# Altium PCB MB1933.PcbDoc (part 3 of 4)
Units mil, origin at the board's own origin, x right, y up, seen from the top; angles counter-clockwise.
Board outline 2755.91 x 3937.01 mil, 4 copper layers (Top Layer, GND, POWER, Bottom Layer), stack 60.63 mil thick; 228 components, 185 nets, 918 pads, 786 vias.
Unrouted connection lines stored in the file: 160.
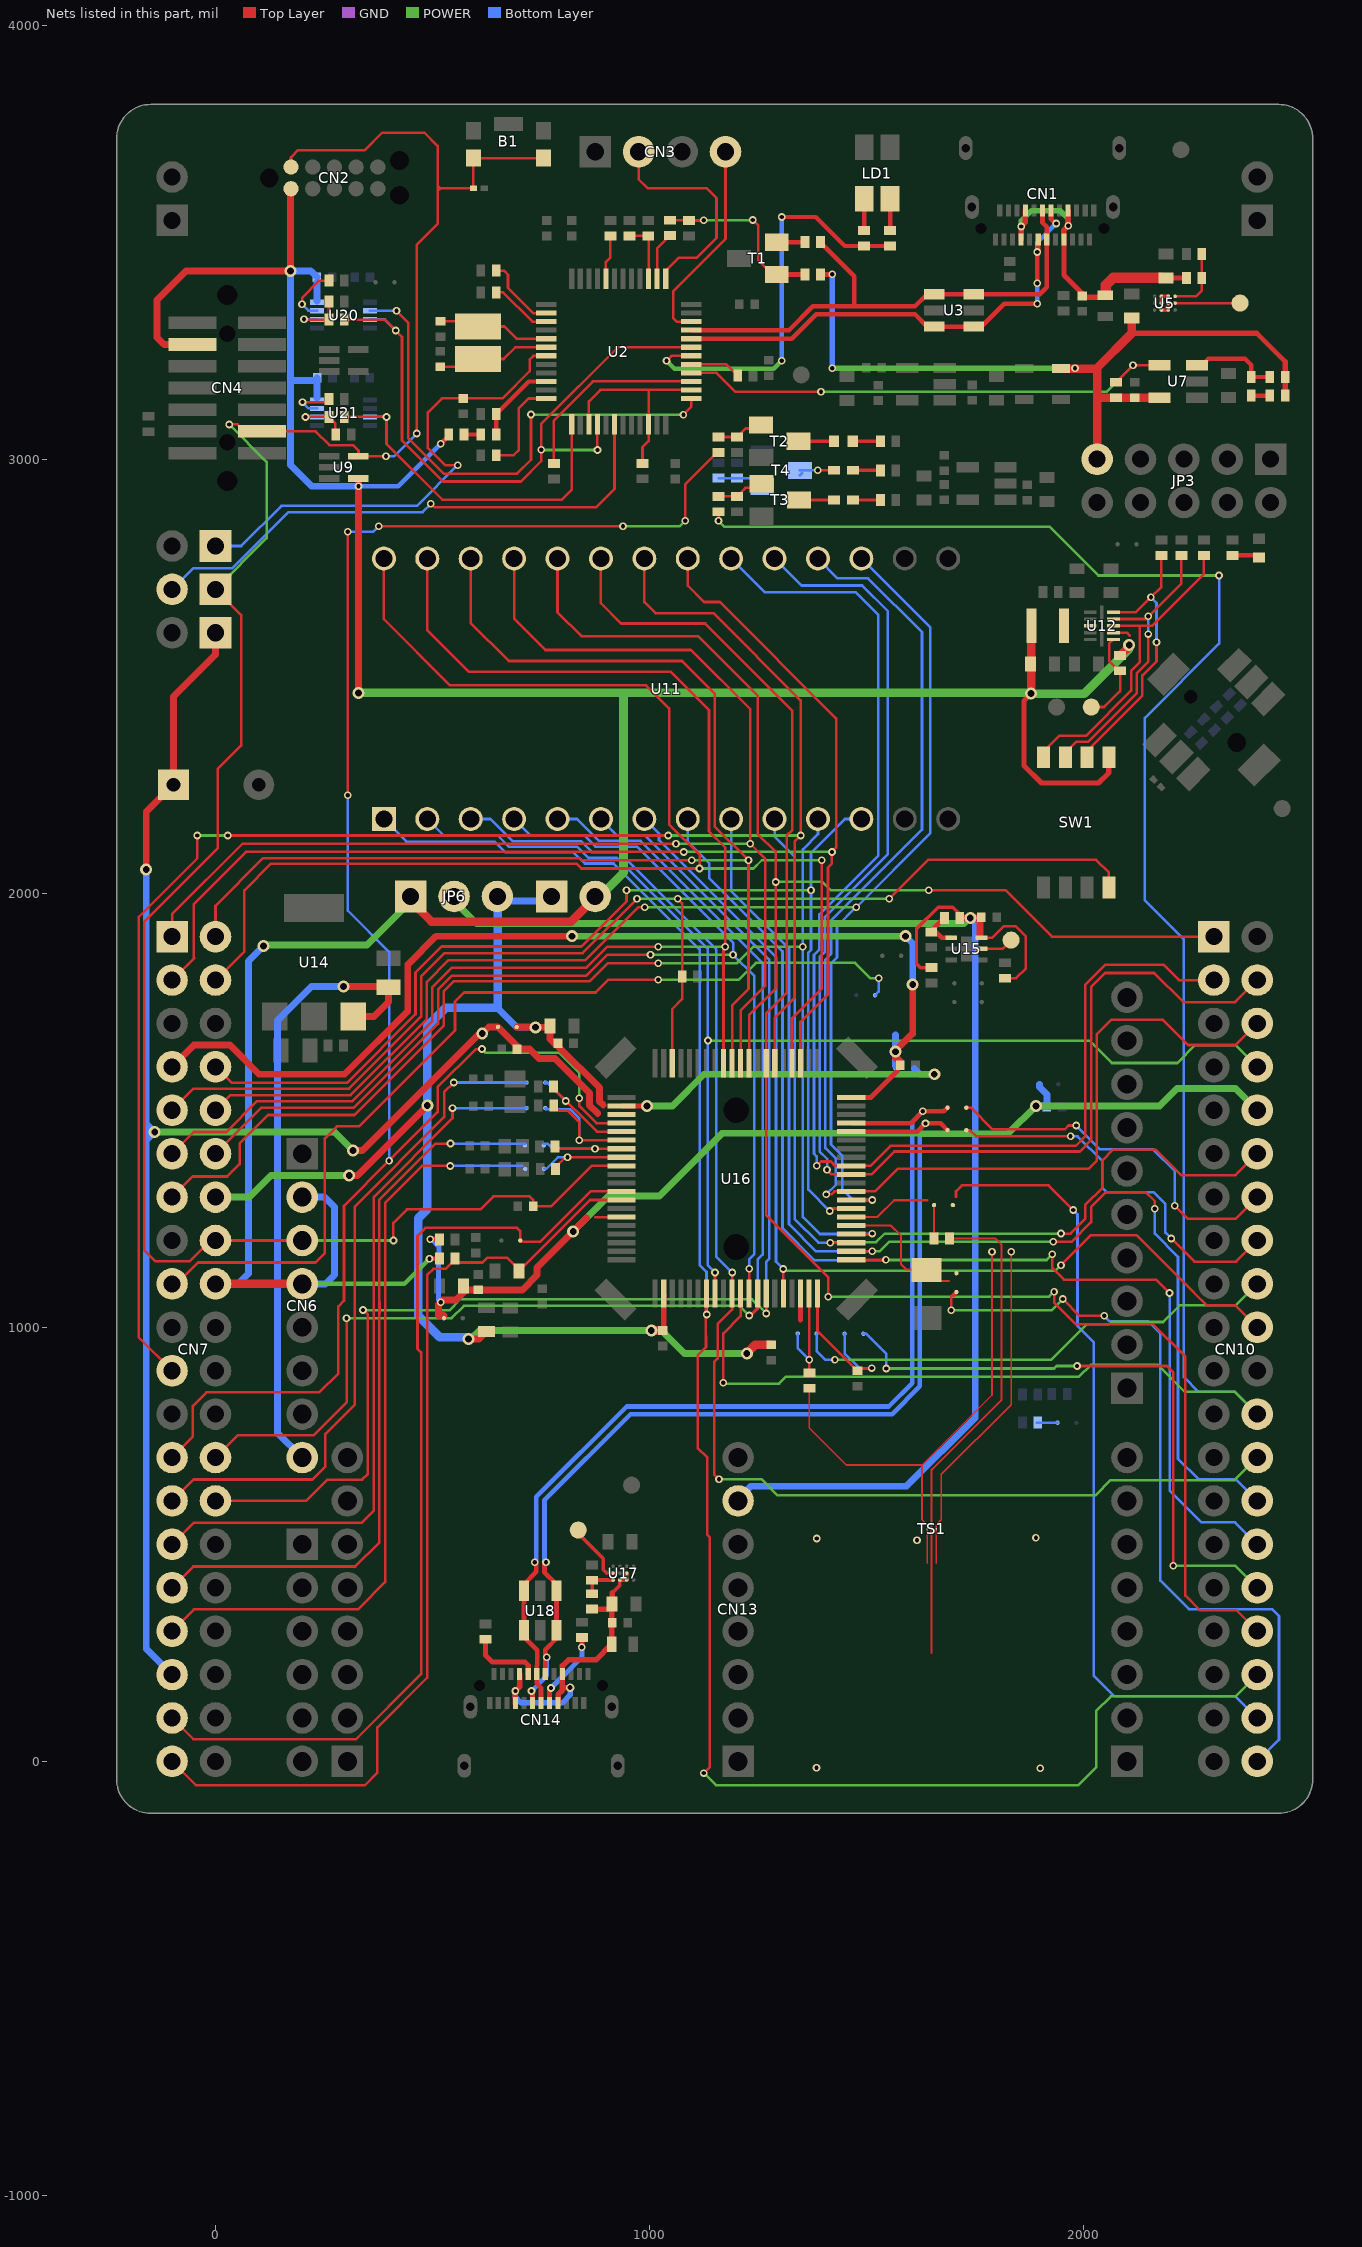
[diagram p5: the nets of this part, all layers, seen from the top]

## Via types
v1: diameter 17.72, hole 9.84, Top Layer to Bottom Layer, tented both sides, 740 vias
v2: diameter 27.56, hole 15.75, Top Layer to Bottom Layer, tented both sides, 45 vias
v3: diameter 19.68, hole 11.81, Top Layer to Bottom Layer, tented both sides, 1 vias

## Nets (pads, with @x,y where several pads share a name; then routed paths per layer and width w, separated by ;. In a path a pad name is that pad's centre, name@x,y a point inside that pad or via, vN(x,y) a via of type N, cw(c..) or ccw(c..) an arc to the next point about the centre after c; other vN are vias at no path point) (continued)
NetCN7_17: CN7.17 SB13.2 | length 2185.5
  Top Layer w5.98: CN7.17@-100,1100 -89.3,1100 -40.05,1149.25 230.25,1149.25 252.02,1171.02 252.02,1435.02 280.03,1463.03 331.03,1463.03 551.76,1683.76 551.76,1750.59 572.48,1771.32 875.78,1771.32 905.41,1800.96 v1(1020,1800.96)
  POWER w5.98: v1(1020,1800.96) 1205.96,1800.96 1244.81,1839.81 1473.28,1839.81 1509.09,1804 v1(1528,1804)
  Bottom Layer w5.98: SB13.2@1519.62,1765 1528,1773.38 v1(1528,1804)
NetCN7_27: CN7.27 SB16.2 | length 1560.7
  Top Layer w5.98: CN7.27@-100,600 -50.65,649.35 223.35,649.35 253.32,679.31 253.32,754.31 321,822 321,1278 527,1484 527,1541.7 v1(549.22,1563.92)
  Bottom Layer w5.98: v1(549.22,1563.92) SB16.2@716.54,1563.92
NetCN7_29: CN7.29 SB18.2 | length 1669.9
  Top Layer w5.98: CN7.29@-100,500 -50.36,549.64 335.96,549.64 364.69,578.37 364.69,1037.03 364.85,1037.19 364.85,1052.81 364.69,1052.97 364.69,1300.38 546,1481.69 v1(546,1505)
  Bottom Layer w5.98: v1(546,1505) 715.75,1505 716.11,1505.35 SB18.2@716.54,1504.92
NetCN7_31: CN7.31 SB19.2 | length 1699.4
  Top Layer w5.98: CN7.31@-100,400 -51,449 321.9,449 377.67,504.77 377.67,1031.65 377.83,1031.81 377.83,1058.19 377.67,1058.35 377.67,1293.99 506.95,1423.27 v1(541.64,1423.27)
  Bottom Layer w5.98: v1(541.64,1423.27) SB19.2@713.09,1423.29
NetCN7_33: CN7.33 SB20.2 | length 1762.6
  Top Layer w5.98: CN7.33@-100,300 -49.67,350.33 328.06,350.33 390.66,412.93 390.66,1026.27 390.82,1026.44 390.82,1063.56 390.66,1063.73 390.66,1286.66 475.79,1371.79 v1(541.15,1371.79)
  Bottom Layer w5.98: v1(541.15,1371.79) 706.7,1371.79
NetCN10_14: CN10.14 SB7.1 | length 851.6
  Top Layer w5.98: SB7.1@1729.77,1505.93 1740.03,1505.93 1790.03,1455.93 1956.52,1455.93 1965.59,1465 v1(1982.95,1465) ; v1(2210,1280) 2240.36,1249.64 2349.64,1249.64 CN10.14@2400,1300
  Bottom Layer w5.98: v1(1982.95,1465) 2037.95,1410 2160,1410 2210,1360 v1(2210,1280)
NetCN10_16: CN10.16 SB8.1 | length 891.2
  Top Layer w5.98: SB8.1@1729.68,1454.17 1737.56,1454.17 1752.7,1439.03 1753.67,1440 v1(1970,1440) ; v1(2201.98,1204.55) 2255.21,1151.32 2351.32,1151.32 CN10.16@2400,1200
  Bottom Layer w5.98: v1(1970,1440) 1986.18,1440 2043.12,1383.06 2043.12,1321.47 2053.24,1311.36 2160.69,1311.36 2188.39,1283.65 2188.39,1218.13 v1(2201.98,1204.55)
NetCN10_18: CN10.18 SB23.1 | length 1136.3
  POWER w5.98: v1(1427,925) 1925,925 2007.47,1007.47 2060.59,1007.47 2065.24,1012.12 2183.15,1012.12 2221.46,1050.43 2350.43,1050.43 CN10.18@2400,1100
  Bottom Layer w5.98: SB23.1@1384.78,985.47 1384.78,945.22 1405,925 v1(1427,925)
NetCN10_32: CN10.32 SB22.1 | length 1435.4
  Top Layer w5.98: v1(1985,910.96) 2191.64,910.96 2206.7,895.9 v1(2206.7,450.82)
  POWER w5.98: v1(1545,905) 1932.01,905 1937.97,910.96 v1(1985,910.96) ; v1(2206.7,450.82) 2349.18,450.82 CN10.32@2400,400
  Bottom Layer w5.98: SB22.1@1492.69,985 1499.25,985 1545,939.25 v1(1545,905)
NetCN10_38: CN10.38 SB9.1 | length 1821.3
  Top Layer w5.98: 1706,1300.47 1706,1313.18 1719.82,1327 1919.39,1327 v1(1976,1270.39)
  Bottom Layer w5.98: v1(1976,1270.39) 1986,1260.39 1986,1003 2023.24,965.76 2023.24,197.77 2071.17,149.84 2350.16,149.84 CN10.38@2400,100
NetCN10_40: CN10.40 SB11.1 | length 1808.8
  Top Layer w5.98: v1(1695,1039) 1695,1071.02 SB11.1@1705.3,1081.31 ; 1702,1072.7 1705.3,1076 ; v1(1952,1065) 1990.68,1026.32 v1(2047.45,1026.32)
  POWER w5.98: v1(1695,1039) 1926,1039 v1(1952,1065)
  Bottom Layer w5.98: v1(2047.45,1026.32) 2060.17,1013.59 2149.35,1013.59 2176.78,986.16 2176.78,416.18 2242.23,350.73 2433.87,350.73 2450.11,334.49 2450.11,50.11 CN10.40@2400,0
NetCN14_A5: CN14.A5 R64.1 | length 165.2
  Top Layer w11.81: R64.1@622,281.28 622,244.48 637.91,228.57 713.2,228.57 720.47,221.3 CN14.A5@720.47,200.98
NetCN14_B5: CN14.B5 R63.1 | length 182
  Top Layer w11.81: CN14.B5@769.68,134.06 769.68,165.68 v1(773,169) ; v1(844,263) R63.1@844,285.28
  Bottom Layer w11.81: v1(773,169) 844,240 v1(844,263)
NetJP5_2: JP5.2 U2.18 | length 1270.8
  Top Layer w5.98: v1(496,2897) 503.69,2889.31 877.31,2889.31 919.16,2931.16 U2.18@919.16,3080.68
  Bottom Layer w5.98: JP5.2@-100,2700 -51,2749 39,2749 168,2878 477,2878 v1(496,2897)
NetL1_1: L1.1 U12.3
NetLD1_1: LD1.1 R7.1 | length 73
  Top Layer w10: R7.1@1554.19,3526.64 LD1.1@1554.19,3599.61
NetLD1_2: LD1.2 R6.2 | length 73.1
  Top Layer w10: R6.2@1494.62,3527.07 LD1.2@1494.62,3600.12
NetLD2_1: LD2.1 R22.1 | length 42.9
  Top Layer w10: LD2.1@2385.8,3146.16 R22.1@2428.75,3146.16
NetLD2_2: LD2.2 R20.1 U7.3 | length 207.9
  Top Layer w10: U7.3@2261.17,3216.37 2272.39,3216.37 2287.45,3231.44 2371.7,3231.44 2385.8,3217.34 LD2.2@2385.8,3189.46 R20.1@2429.08,3189.49
NetLD3_1: LD3.1 R32.1 | length 119.2
  Top Layer w5.98: LD3.1@1476.22,3041.28 R32.1@1531.9,3041.28
  Top Layer w7.87: LD3.1@1468.34,3041.28 1476.22,3041.28 R32.1@1531.9,3041.28
NetLD3_2: LD3.2 T2.3 | length 89.5
  Top Layer w5.98: T2.3@1343.44,3033.3 T2.3@1351.32,3033.3
  Top Layer w8: T2.3@1343.44,3041.28 LD3.2@1425.04,3041.28
NetLD4_1: LD4.1 R36.1 | length 119.2
  Top Layer w5.98: LD4.1@1476.22,2974.16 R36.1@1531.9,2974.16
  Top Layer w8: LD4.1@1468.34,2974.16 R36.1@1531.9,2974.16
NetLD4_2: LD4.2 T4.3 | length 85.6
  Top Layer w5.98: v1(1387.31,2974.16) LD4.2@1425.04,2974.16
  Bottom Layer w5.98: T4.3@1346.27,2974.16 v1(1387.31,2974.16) ; T4.3@1346.69,2963.13 T4.3@1351.51,2967.95
NetLD5_1: LD5.1 R39.1 | length 63.6
  Top Layer w5.98: LD5.1@1468.34,2905.94 R39.1@1531.9,2905.94
NetLD5_2: LD5.2 T3.3 | length 80.9
  Top Layer w5.98: T3.3@1344.1,2905.94 LD5.2@1425.04,2905.94
NetLD6_1: LD6.1 R42.2 | length 56.1
  Top Layer w10: R42.2@2343,2778.29 LD6.1@2399.08,2778.29
NetR1_1: R1.1 R5.2 R12.1 T1.1 | length 411.4
  Top Layer w5.98: R1.1@1046.9,3550.57 1090.14,3550.57 R5.2@1091,3549.72 1124,3549.72 v1(1124.71,3550.43) ; v1(1237.51,3551.12) 1250.6,3538.03 1250.6,3458.01 1283.6,3425.01 T1.1@1292.98,3425.01
  Top Layer w11.81: T1.1@1292.98,3425.01 R12.1@1358.28,3425
  POWER w5.98: v1(1124.71,3550.43) 1236.82,3550.43 v1(1237.51,3551.12)
NetR2_2: R2.2 U2.44 | length 103.2
  Top Layer w5.98: U2.44@899.47,3415.32 899.47,3454.72 909.75,3465 R2.2@909.75,3514.31
NetR8_2: R8.2 T1.2 | length 65.4
  Top Layer w5.98: R8.2@1358.1,3499.81 R8.2@1358.28,3500
  Top Layer w10.63: T1.2@1292.98,3499.81 R8.2@1358.1,3499.81
NetR9_2: R9.2 R13.1 U5.C1 | length 150.8
  Top Layer w5.98: U5.C1@2210.79,3375.25 2259.11,3375.25 2272.31,3388.45 R13.1@2272.31,3417.29 R9.2@2272.31,3472.31
NetR11_1: R11.1 U2.2 | length 173.2
  Top Layer w5.98: R11.1@646.72,3434.38 664.29,3434.38 673.83,3424.84 673.83,3394.58 731.82,3336.58 U2.2@761.68,3336.58
NetR14_1: R14.1 U20.7 | length 134.1
  Top Layer w5.98: v1(199.52,3356.63) 199.52,3371.81 238.96,3411.25 R14.1@261.51,3411.25
  Bottom Layer w5.98: v1(199.52,3356.63) 214.13,3342.01 233.78,3342.01 U20.7@233.95,3341.84
NetR15_1: R15.1 U2.3 | length 142.9
  Top Layer w5.98: R15.1@646.72,3384.38 662.81,3384.38 730.29,3316.9 U2.3@761.68,3316.9
NetR17_1: R17.1 R18.2 U20.6 | length 129.8
  Top Layer w5.98: v1(204.01,3322.16) 204.01,3322.01 204.69,3321.34 R18.2@261.51,3321.34 R17.1@261.51,3363.25
  Bottom Layer w5.98: v1(204.01,3322.16) U20.6@233.95,3322.16
NetR19_1: R19.1 U2.29 | length 117.3
  Top Layer w5.98: U2.29@1096.32,3218.47 1176.96,3218.47 R19.1@1202.89,3192.55
NetR23_1: R23.1 U21.7 | length 103.6
  Top Layer w5.98: v1(200.4,3131.44) 254.62,3131.44 R23.1@261.51,3138.32
  Bottom Layer w5.98: v1(200.4,3131.44) 214.7,3117.14 233.95,3117.14 U21.7@233.95,3116.98
NetR25_2: R25.2 R27.1 U21.6 | length 128.6
  Top Layer w5.98: v1(207.29,3097.28) 261.22,3097.28 R25.2@261.51,3097.58 275.9,3083.18 275.9,3057.22 R27.1@277.17,3057.22
  Bottom Layer w5.98: v1(207.29,3097.28) U21.6@233.95,3097.29
NetR30_2: R30.2 R31.2 T2.1 | length 105.6
  Top Layer w5.98: R30.2@1159.36,3051.02 R31.2@1201.29,3051.02 1220.97,3070.71 T2.1@1256.83,3070.71
NetR37_2: R37.2 R38.2 T3.1 | length 106.3
  Top Layer w5.98: R37.2@1159.35,2914.11 R38.2@1201.28,2914.11 1220.97,2933.8 T3.1@1257.52,2933.8
NetR40_2: R40.2 SW1.7 U12.10 | length 675.2
  Top Layer w5.98: SW1.7@1958,2313 1958,2324 1982.95,2348.95 2010.3,2348.95 2108.16,2446.81 2108.45,2446.81 2122.52,2460.88 2122.52,2506.88 2149,2533.36 v1(2149,2597) ; U12.10@2068.58,2631.75 2142.87,2631.75 v1(2149.12,2638) 2225,2713.88 R40.2@2225,2778.29
  Bottom Layer w5.98: v1(2149,2597) 2149,2637.88 v1(2149.12,2638)
NetR41_2: R41.2 SW1.8 U12.9 | length 731.9
  Top Layer w5.98: SW1.8@1908,2313 1908,2327 1943.51,2362.51 2005.49,2362.51 2109.53,2466.55 2109.53,2512.53 2129.63,2532.63 2129.63,2616 ; U12.9@2068.58,2616 2129.63,2616 ; R41.2@2277,2778.29 2277,2735.43 2157.57,2616 2129.63,2616
NetR43_2: R43.2 SW1.6 U12.11 | length 651.8
  Top Layer w5.98: SW1.6@2008,2313 2008,2328 2135.5,2455.5 2135.5,2501.5 2168,2534 v1(2168,2578) ; U12.11@2068.58,2647.5 2120.5,2647.5 v1(2155,2682) 2179,2706 R43.2@2179,2778.28 ; R43.2@2173,2778.29 R43.2@2176,2775.28
  Bottom Layer w5.98: v1(2155,2682) 2168,2669 v1(2168,2578)
NetR45_2: R45.2 TP4.1 U12.7 | length 216.1
  Top Layer w5.98: TP4.1@2017.6,2429 2047.08,2429 2084,2465.92 R45.2@2084,2512.28 2081.48,2512.28 2058.96,2534.81 2058.96,2574.89 U12.7@2068.58,2584.51
NetR46_1: R46.1 R47.2 U15.4 | length 90.3
  Top Layer w10.63: R47.2@1649,1913.72 1677.6,1942.31 R46.1@1682.28,1942.31 ; R47.2@1656.72,1913.72 1673.15,1897.28 U15.4@1695.04,1897.28
NetR61_2: R61.2 R62.1 U17.C1 | length 79.2
  Top Layer w8.46: R62.1@867.78,386.43 R61.2@867.78,417 868.78,418 U17.C1@916.02,418
NetR65_2: R65.2 R66.2 T4.1 | length 108.5
  Bottom Layer w5.98: R66.2@1159.35,2956.44 1231.3,2956.44 1250.99,2936.76 T4.1@1259.65,2936.76
NetR73_1: R73.1 SB24.2 | length 47.7
  Bottom Layer w5.98: R73.1@1892.32,780.3 SB24.2@1939.98,780.3
NetTP1_1: TP1.1 U5.B1 | length 149.6
  Top Layer w5.98: U5.B1@2210.79,3359.51 TP1.1@2360.4,3359.51
NetTP5_1: TP5.1 U15.2 | length 76.3
  Top Layer w5.98: U15.2@1765.12,1871.69 1812.69,1871.69 TP5.1@1833,1892
NetTP6_1: TP6.1 U17.B1 | length 141.1
  Top Layer w8.46: TP6.1@835.7,532.9 835.7,524.83 893.39,467.14 893.39,441.61 901.25,433.75 U17.B1@916.02,433.75
NRST: B1.2 B1.4 C40.2 CN2.10 CN4.12 CN6.3 CN7.16 JP5.1 U1.1 U9.5 U16.9 | length 5249.7
  Top Layer w5.98: JP5.1@0,2700 59,2641 59,2340.42 5,2286.42 5,2103.46 -163.77,1934.68 -163.77,1177.5 -138.86,1152.58 -58.96,1152.58 -11.55,1200 CN7.16@0,1200 CN6.3@200,1200 ; v1(32,3080) 51,3080 67,3064 CN4.12@107,3064 230.93,3064 262.48,3032.44 316.8,3032.44 329.42,3019.82 U9.5@329.42,3006.84 372.63,3006.84 372.78,3007 v1(393,3007) ; CN2.10@174,3673 174,3695.5 190.5,3712 344,3712 384,3752 482,3752 512,3722 512,3630 ; v1(410,1200) 410,1240.6 441.28,1271.89 610.15,1271.89 640.16,1301.91 723.38,1301.91 732,1293.29 C40.2@732,1279.07 773.67,1279.07 866.64,1372.04 U16.9@935.23,1372.04 ; v1(464,3059) 464,3494 512,3542 512,3617.52 ; U1.1@592.43,3623.76 518.24,3623.76 ; U1.1@594.7,3623.76 594.29,3624.16 B1.4@594.29,3693.5 B1.2@755.71,3693.5 ; 512,3617.52 512,3630 ; 512,3617.52 518.24,3623.76 ; 512,3630 518.24,3623.76
  POWER w5.98: JP5.1@0,2700 118,2818 118,2994 v1(32,3080) ; CN6.3@200,1200 200.26,1199.74 201.24,1200.73 202.03,1199.94 202.09,1200 v1(410,1200)
  Bottom Layer w5.98: v1(393,3007) 412,3007 v1(464,3059)
PA11: CN14.A7 CN14.B7 SB8.2 U16.56 U18.3 U18.4 | length 2367.8
  Top Layer w10.63: v1(728,162) 730.31,159.69 CN14.B7@730.31,134.06 ; CN14.A7@759.84,200.98 759.84,220.08 759.69,220.23 759.69,257.28 785.58,283.17 U18.3@785.58,302 U18.4@785.58,392.55 785.58,408 757.87,435.71 757.87,455.46 v1(761.41,459) ; U16.56@1464.76,1450.78 1616.63,1450.78 v1(1635.6,1469.76) 1670.79,1469.76 SB8.2@1686.38,1454.17
  Bottom Layer w10.63: v1(728,162) 763,197 v1(763,240) ; v1(761.41,459) 757.87,462.54 757.87,601.7 956.17,800 1558.7,800 1622.68,863.98 1622.68,1456.84 v1(1635.6,1469.76)
PA12: CN14.A6 CN14.B6 SB7.2 U16.57 U18.1 U18.6 | length 2354.2
  Top Layer w10.63: v1(735.82,459) 739.37,455.46 739.37,436.59 710.78,408 U18.6@710.78,392.55 U18.1@710.78,302 716.05,296.73 716.05,281.28 741.18,256.15 741.18,221.11 740.16,220.08 CN14.A6@740.16,200.98 740.16,179.79 750,169.94 CN14.B6@750,134.06 ; U16.57@1464.76,1470.47 1602.52,1470.47 v1(1629.6,1497.55) 1678.08,1497.55 SB7.2@1686.46,1505.93
  Bottom Layer w10.63: v1(735.82,459) 739.37,462.54 739.37,609.37 947.63,817.63 1551.4,817.63 1605.06,871.29 1605.06,1473 v1(1629.6,1497.55)
PB1: CN10.26 U11.3 U16.30 | length 3238.8
  Top Layer w5.98: v1(1160,650) 1149,661 1149,920.02 1157.02,928.03 1157.02,1007.38 1190.15,1040.52 U16.30@1190.15,1077.76 v1@1190.15,1125.89
  POWER w5.98: v1(1160,650) 1258,650 1295.02,612.98 2026.98,612.98 2062,648 2348,648 CN10.26@2400,700
  Bottom Layer w5.98: U11.3@588,2171 633.47,2171 684.51,2119.97 841.71,2119.97 867.18,2094.5 929.99,2094.5 1153.45,1871.03 1153.45,1163.03 v1(1190.37,1126.11)
PB2: CN10.24 R37.1 U16.31 | length 4912.2
  Top Layer w5.98: v1(1159.06,2857.81) 1159.35,2858.11 R37.1@1159.35,2878.68 ; v1(1170,872) 1170,985.91 1209.84,1025.75 U16.31@1209.84,1077.76
  POWER w5.98: v1(1159.06,2857.81) 1172.88,2844 1922,2844 2034,2732 v1(2312,2732) ; v1@1170,874.98 v1@1170,874.5 ; CN10.24@2400,800 2348.49,851.51 2232.98,851.51 2170.9,913.59 2016.49,913.59 1989.05,886.15 1314.17,886.15 1298.17,870.15 1171.85,870.15 v1(1170,872) ; v1(1170,872) 1167.5,872 v1@1170,874.5 ; v1(1170,872) v1@1170,874.5
  Bottom Layer w5.98: v1(2312,2732) 2312,2575 2141.06,2404.06 2141.06,1983.58 2230.72,1893.92 2230.72,885.57 2264.77,851.51 2348.49,851.51 CN10.24@2400,800
PB11: CN10.20 U11.7 U16.36 | length 2444.2
  Top Layer w5.98: U16.36@1308.26,1077.76 v1(1308.27,1134.29) ; v1(1948,1143) 2017.12,1212.12 2122.27,1212.12 2253.59,1080.8 2283.94,1050.43 2349.57,1050.43 CN10.20@2400,1000
  POWER w5.98: v1(1308.27,1134.29) 1312.07,1130.5 1935.5,1130.5 v1(1948,1143) v1@1951.34,1143
  Bottom Layer w5.98: U11.7@988,2171 1021.74,2137.26 1021.74,2122.5 1291.35,1852.89 1291.35,1151.22 v1(1308.27,1134.29)
PB12: R60.1 SB23.2 U16.39 | length 254.5
  Top Layer w5.98: U16.39@1367.32,1077.76 1368,1077.08 v1(1368,925) R60.1@1368,895
  Bottom Layer w5.98: SB23.2@1341.48,985.47 1341.48,951.53 v1(1368,925)
PB13: C50.1 SB22.2 U16.40 | length 373.5
  Top Layer w5.98: U16.40@1387,1077.76 1387,991.74 C50.1@1479,899.74 1485.26,906 v1(1512,906)
  Bottom Layer w5.98: SB22.2@1449.38,985 1449.38,939.86 1483.24,906 v1(1512,906)
PB14: CN10.30 U11.8 U16.41 | length 2804.3
  Top Layer w5.98: U16.41@1464.76,1155.51 v1(1544.5,1155.51) ; v1(1928,1168.38) 1928,1136.34 1954.34,1110 2167,1110 v1(2198,1079)
  POWER w5.98: v1(1544.5,1155.51) 1544.85,1155.15 1914.77,1155.15 v1(1928,1168.38)
  Bottom Layer w5.98: U11.8@1088,2171 1088,2119 1138,2069 1138,2034.43 1306.34,1866.09 1306.34,1228.66 1380.5,1154.5 v1@1544.5,1154.5 ; v1(2198,1079) 2198,624.58 2271.86,550.73 2349.27,550.73 CN10.30@2400,500
PB15: CN10.28 U11.9 U16.42 | length 2829.1
  Top Layer w5.98: U16.42@1464.76,1175.19 v1(1513.11,1175.18) ; v1(1930,1197) 1972,1197 2017.15,1242.15 2017.15,1276.67 2051.84,1311.36 2143.05,1311.36 2164,1290.41 v1(2164,1273)
  POWER w5.98: v1(1513.11,1175.18) 1530.07,1175.18 1551.89,1197 v1(1930,1197)
  Bottom Layer w5.98: U11.9@1188,2171 1188,2005.65 1321.17,1872.48 1321.17,1237.83 1383.97,1175.03 1512.96,1175.03 v1(1513.11,1175.18) ; v1(2164,1273) 2164,1215.87 2217.43,1162.44 2217.43,697.11 2264.3,650.23 2349.77,650.23 CN10.28@2400,600
PC2: CN7.37 SB10.2 U16.12 | length 2222.6
  Top Layer w5.98: CN7.37@-100,100 -51,51 324,51 474.02,201.02 474.02,941.98 465.49,950.51 465.49,1210.49 483.94,1228.94 694.93,1228.94 701.98,1221.89 SB10.2@701.98,1200.04 701.98,1197.08 748.18,1197.08 864.08,1312.99 U16.12@935.23,1312.99
PC3: C43.2 CN7.39 R58.2 U16.13 | length 2257.9
  Top Layer w5.98: CN7.39@-100,0 -45,-55 344,-55 373,-26 373,78 487.65,192.65 487.65,1120.26 502.22,1134.83 530.33,1134.83 551.58,1156.08 R58.2@551.58,1158.6 560.83,1149.35 615.16,1149.35 625.79,1159.98 672.45,1159.98 699.32,1133.11 C43.2@699.32,1129.96 699.42,1129.96 862.76,1293.3 U16.13@935.23,1293.3 U16.13@934.33,1294.21
PC4: CN10.36 U11.1 U16.27 | length 4298.9
  Top Layer w5.98: v1(1125,-27) 1139,-13 1139,515.98 1132.98,522 1132.98,699.89 1111,721.87 1111,935.14 1130.08,954.21 1130.08,979.68 1129.44,980.32 1129.44,1076.09 U16.27@1131.1,1077.76
  POWER w5.98: v1(1125,-27) 1152.81,-54.81 1987.83,-54.81 2029,-13.64 2029,116 2062.84,149.84 2349.84,149.84 CN10.36@2400,200
  Bottom Layer w5.98: U11.1@388,2171 440,2119 643.07,2119 668.07,2094 825.27,2094 850.74,2068.53 917.47,2068.53 1115.61,1870.39 1115.61,1143.2 1131.15,1127.66 1131.15,1030.02 v1(1131.8,1029.37)
PC5: CN10.8 U11.2 U16.28 | length 2896
  Top Layer w5.98: U16.28@1150.78,1077.76 1150.78,1125.89 v1(1151,1126.11)
  POWER w5.98: v1(1134.46,1660.57) 2013.29,1660.57 2065.05,1608.81 2215.92,1608.81 2257.11,1650 2350,1650 CN10.8@2400,1600
  Bottom Layer w5.98: U11.2@488,2171 526.56,2132.44 650.83,2132.44 676.29,2106.98 833.49,2106.98 858.96,2081.51 924.49,2081.51 1134.46,1871.54 v1(1134.46,1660.57) 1134.46,1142.71 1151,1126.17 v1(1151,1126.11)
PC6: CN10.6 U11.18 U16.49 | length 3091.9
  Top Layer w5.98: v1(1406.78,1306.22) 1419.22,1306.22 1425.99,1312.99 U16.49@1464.76,1312.99 1519.66,1312.99 1571.68,1365 2011.66,1365 2030.13,1383.47 2030.13,1674.75 2064.18,1708.8 2182.19,1708.8 2240.56,1650.43 2350.43,1650.43 CN10.6@2400,1700
  Bottom Layer w5.98: U11.18@1388,2771 1433.37,2725.63 1503.55,2725.63 1627.66,2601.51 1627.66,2146.66 1417.92,1936.92 1417.92,1860.18 1404.94,1847.19 1404.94,1413.14 1429,1389.08 1429,1328.44 v1(1406.78,1306.22)
PC8: CN10.4 U11.19 U16.51 | length 3113.3
  Top Layer w5.98: v1(1409,1363) 1419.64,1352.36 U16.51@1464.76,1352.36 1511.36,1352.36 1564,1405 1991.18,1405 2017.15,1430.97 2017.15,1784.1 2049.24,1816.18 2162.4,1816.18 2229.63,1748.95 2348.95,1748.95 CN10.4@2400,1800
  Bottom Layer w5.98: U11.19@1288,2771 1350.1,2708.9 1489.67,2708.9 1548.92,2649.64 1548.92,2090.56 1404,1945.64 1404,1864.62 1391.95,1852.57 1391.95,1405.38 1409,1388.33 v1(1409,1363)
PC9: CN10.3 U11.20 U16.52 | length 3060.4
  Top Layer w5.98: v1(1385,1372) 1395,1382 1417.64,1382 1427.6,1372.04 U16.52@1464.76,1372.04 1509.03,1372.04 1554.97,1417.98 1981.89,1417.98 2004.16,1440.26 2004.16,1789.47 2049.96,1835.27 2184.36,1835.27 2219.63,1800 CN10.3@2300,1800
  Bottom Layer w5.98: U11.20@1188,2771 1265.66,2693.34 1475.2,2693.34 1527.07,2641.47 1527.07,2087.07 1391,1951 1391,1869.98 1378.97,1857.95 1378.97,1400 1385,1393.97 v1(1385,1372)
PC10: CN7.3 U11.21 U16.63 | length 3077.5
  Top Layer w5.98: CN7.3@-100,1800 -50,1850 ; -48.68,1851.32 -50,1850 ; v1@1079,2095.15 70.15,2095.15 -50,1975 -50,1850 ; U11.21@1088,2771 1088,2708.47 1125.47,2671 1162,2671 1430,2403 1430,2105 v1(1420.15,2095.15) 1420.15,2068.15 1411,2059 1411,1767 1347.63,1703.63 U16.63@1347.63,1608.26
  POWER w5.98: v1(1079,2095) 1079.15,2095.15 v1(1420.15,2095.15)
PC11: CN7.4 U11.28 U16.64 | length 3380
  Top Layer w5.98: CN7.4@0,1800 1.11,1800 66.67,1865.56 66.67,2006.67 128.08,2068.08 831.99,2068.08 843.07,2057 v1(1115,2057) 1115.85,2057.85 1115.85,2087.94 1045.09,2158.7 1045.09,2425.91 992,2479 540.2,2479 388,2631.2 U11.28@388,2771 ; U16.64@1327.95,1608.26 1327.95,1711.95 1397,1781 v1(1397,2076)
  POWER w5.98: v1(1115,2057) 1239.49,2057 1258.49,2076 v1(1397,2076)
PC13: CN7.25 R30.1 U16.4 | length 4301.4
  Top Layer w5.98: CN7.25@-100,700 -52,748 -52,819 -21,850 239,850 283,894 283,1048.48 296,1061.48 296,1280 v1(400,1384) 512,1496 512,1553.35 599.63,1640.98 v1(614,1640.98) ; v1(305,2226) 305.11,2226.11 v1@305.11,2833 ; v1(376.19,2845.31) v1(938.79,2845.31) ; v1(838.1,1527.99) 838.1,1509.69 877.33,1470.47 U16.4@935.23,1470.47 ; v1(1082,2858.11) 1082,2941.87 1155.72,3015.59 R30.1@1159.36,3015.59
  POWER w5.98: v1(614,1640.98) 622.17,1632.82 791.24,1632.82 838.1,1585.96 v1(838.1,1527.99) ; v1(938.79,2845.31) 1069.2,2845.31 v1(1082,2858.11)
  Bottom Layer w5.98: v1(305,2226) 305,1959.64 400,1864.64 v1(400,1384) ; v1(305,2833) 363.88,2833 v1(376.19,2845.31)
PC14: R52.2 SB16.1 U16.5 | length 277.5
  Top Layer w5.98: R52.2@782.59,1549.26 780.17,1549.26 878.61,1450.82 886.72,1450.82 ; 878.55,1450.78 U16.5@935.23,1450.78
  Bottom Layer w5.98: SB16.1@759.85,1562.05 766.17,1562.05 ; SB16.1@759.85,1563.92 764.3,1563.92 766.17,1562.05 ; v1(806.96,1521.25) 766.17,1562.05
PC15: R53.2 SB18.1 U16.6 | length 345.5
  Top Layer w5.98: R53.2@779.19,1510.83 790.82,1499.2 810.96,1499.2 838.1,1472.07 v1(838.1,1431.14) ; v1@843.61,1431.1 U16.6@935.23,1431.1
  Bottom Layer w5.98: SB18.1@759.85,1504.92 762.36,1502.4 816.71,1502.4 838.1,1481.02 v1(838.1,1431.14)
PD0: CN7.21 U11.22 U16.66 | length 4125.6
  Top Layer w5.98: CN7.21@-100,900 -176.76,976.76 -176.76,1945.42 -42,2080.18 v1(-42,2133) ; v1(28,2133) v1(1043,2133) ; U11.22@988,2771 988,2670.8 1013.59,2645.21 1146.79,2645.21 1348.05,2443.95 v1(1348.05,2133) 1334.15,2119.1 1334.15,1869.19 1334.6,1868.74 1334.6,1759.6 1288.58,1713.58 U16.66@1288.58,1608.26
  POWER w5.98: v1(-42,2133) v1(28,2133) ; v1(1043,2133) v1(1348.05,2133)
PD1: CN10.34 U11.23 U16.67 | length 3734.5
  Top Layer w5.98: U11.23@888,2771 888,2668.05 934.75,2621.3 1127.96,2621.3 1329.14,2420.12 1329.14,2146 1316,2132.86 1316,1770.66 1268.89,1723.55 U16.67@1268.89,1608.26 1268.89,1258.11 1411.42,1115.58 v1(1411.42,1070.61) ; v1(1932,1082) 1932,1057.57 1982.74,1006.83 2160.17,1006.83 2234.46,932.54 2234.46,381.63 2267.92,348.17 2351.83,348.17 CN10.34@2400,300
  POWER w5.98: v1(1411.42,1070.61) 1920.61,1070.61 v1(1932,1082)
PD3: CN10.1 U11.24 U16.69 | length 2615.7
  Top Layer w5.98: U11.24@788,2771 788,2647.08 842.72,2592.36 1111.89,2592.36 1249.22,2455.03 1249.22,2136.65 1291,2094.87 v1(1291,2026) 1291,1781.09 1229.52,1719.61 U16.69@1229.52,1608.26 ; v1(1643,2007) 1819.81,2007 1926.81,1900 CN10.1@2300,1900
  POWER w5.98: v1(1291,2026) 1398.23,2026 1417.55,2006.67 1417.88,2007 v1(1643,2007)
PD4: CN7.1 U11.25 U16.70 | length 3073.6
  Top Layer w5.98: CN7.1@-100,1900 -100,1952 62,2114 v1(1061,2114) ; U11.25@688,2771 688,2632.52 760.05,2560.47 1095.53,2560.47 1232,2424 v1(1232,2114) 1266.64,2079.36 1266.64,1786.95 1209.84,1730.15 U16.70@1209.84,1608.26
  POWER w5.98: v1(1061,2114) v1(1232,2114)
PD5: CN7.2 U11.26 U16.71 | length 3024.2
  Top Layer w5.98: CN7.2@0,1900 0,1971.09 109.97,2081.06 837.37,2081.06 842.43,2076 v1(1097,2076) ; U11.26@588,2771 588,2622.87 675.87,2535 1075,2535 1149.98,2460.02 1149.98,2154 1227.96,2076.02 1227.96,1779.37 1190.15,1741.56 U16.71@1190.15,1608.26
  POWER w5.98: v1(1097,2076) v1(1228.16,2076)
PD6: CN7.11 U11.27 U16.72 | length 3238
  Top Layer w5.98: CN7.11@-100,1400 -50.06,1449.94 25.03,1449.94 96.09,1521 315.55,1521 499.82,1705.27 499.82,1783.84 543.97,1828 853.74,1828 902.74,1877 v1(1020,1877) ; U11.27@488,2771 488,2605.55 583.55,2510 1049,2510 1137,2422 1137,2142.52 1174.41,2105.11 v1(1174.41,1877) ; U16.72@1170.47,1608.26 1170.47,1868.47 v1@1176.7,1874.7
  POWER w5.98: v1(1020,1877) v1(1174.41,1877)
PD8: CN10.12 U11.10 U16.43 | length 2257.5
  Top Layer w5.98: v1(1416.41,1194.89) U16.43@1464.76,1194.88 ; v1@1948,1215.87 1969.87,1215.87 2004.16,1250.16 2004.16,1282.52 2043.12,1321.47 2043.12,1384.78 2067.72,1409.39 2165.66,1409.39 2224.61,1350.43 2350.43,1350.43 CN10.12@2400,1400
  POWER w5.98: v1(1416.41,1194.89) 1417.55,1196.03 1522.03,1196.03 1541.87,1215.87 1938.3,1215.87
  Bottom Layer w5.98: U11.10@1288,2171 1288,2131 1334.15,2084.85 1334.15,1249.7 1388.96,1194.89 v1(1416.41,1194.89)
  other v1: 1948,1216
PD9: CN7.13 U11.11 U16.44 | length 2926.7
  Top Layer w5.98: CN7.13@-100,1300 -52.58,1347.42 27.02,1347.42 55.47,1375.87 55.47,1423.47 121,1489 320.27,1489 525.79,1694.51 525.79,1773.09 549.99,1797.29 862.4,1797.29 904.11,1839 v1(1020,1839) ; U16.44@1464.76,1214.56 v1@1513.1,1214.56
  POWER w5.98: v1(1020,1839) 1202,1839 1240,1877 v1(1353,1877) v1@1358.1,1877
  Bottom Layer w5.98: U11.11@1388,2171 1388,2136 1353,2101 1353,2014.53 1352.95,2014.48 1352.95,1998.87 1353,1998.82 v1(1353,1877) 1353,1254.15 1392.15,1215 v1@1512.69,1215
  other v1: 1513.1,1215.88
PD10: C42.1 SB11.2 U16.45 | length 301.1
  Top Layer w5: U16.45@1464.76,1234.25 1556.25,1234.25 1579.63,1210.86 1579.63,1144.82 1591.29,1133.16 1624.04,1133.16 C42.1@1648.58,1108.62 ; C42.1@1663.12,1107 1689.67,1107
PD11: R56.1 SB9.2 U16.46 | length 269.4
  Top Layer w5: U16.46@1464.76,1253.93 1524.81,1253.93 1563.46,1292.58 1639.86,1292.58 ; R56.1@1655.52,1203.29 SB9.2@1655.46,1281.61
PD12: CN7.8 U11.12 U16.47 | length 2686.7
  Top Layer w5.98: CN7.8@0,1600 0.57,1600 37.57,1563 302.46,1563 460.87,1721.4 460.87,1817.37 520.73,1877.23 842.92,1877.23 946.91,1981.22 v1(946.91,2006.67) ; v1@1416.42,1273.62 U16.47@1464.76,1273.62
  POWER w5.98: v1(946.91,2006.67) v1@1372,2006.67
  Bottom Layer w5.98: v1(1415,1268) 1365.98,1317.02 1365.98,1863.33 1371.85,1869.19 1371.85,1945.94 1372,1946.09 v1(1372,2007) 1372,2093 1450,2171 U11.12@1488,2171
PD13: CN7.10 U11.17 U16.48 | length 3472.2
  Top Layer w5.98: CN7.10@0,1500 35,1535 311.19,1535 486.83,1710.65 486.83,1795.83 537,1846 852.03,1846 974.03,1968 v1(989,1968) ; U16.48@1464.76,1293.3 v1(1513.11,1293.31)
  POWER w5.98: v1(989,1968) v1(1476,1968)
  Bottom Layer w5.98: v1(1476,1968) 1431.94,1923.94 1431.94,1852.43 1417.92,1838.41 1417.92,1421.3 1444.22,1394.99 1444.22,1317.78 1468.69,1293.31 v1(1513.11,1293.31) ; v1@1476.28,1967.72 1646.99,2138.44 1646.99,2612.01 U11.17@1488,2771
PE7: CN7.12 U11.4 U16.32 | length 2875.4
  Top Layer w5.98: CN7.12@0,1400 106,1506 318.91,1506 512.8,1699.89 512.8,1778.47 544.61,1810.27 854.38,1810.27 902.11,1858 v1(1002,1858) ; U16.32@1229.52,1077.76 v1@1229.52,1126.1
  POWER w5.98: v1(1002,1858) v1(1192.41,1858)
  Bottom Layer w5.98: U11.4@688,2171 726.05,2132.95 849.93,2132.95 875.4,2107.48 971.4,2107.48 1170.44,1908.44 1170.44,1907.63 1193.26,1884.81 1193.26,1858.85 v1(1192.41,1858) 1241.35,1809.06 1241.35,1554.25 ; v1(1229.53,1134.68) 1229.53,1156.57 1241.35,1168.38 1241.35,1553.25
PE8: CN7.26 U11.5 U16.33 | length 3002.3
  Top Layer w5.98: CN7.26@0,700 51,751 226,751 302,827 v1(302,1021) ; v1@1229.53,1023.71 v1(1229.53,1027.01) 1232.71,1027.01 1249.21,1043.5 U16.33@1249.21,1077.76
  POWER w5.98: v1(302,1021) 544,1021 572.22,1049.22 707.88,1049.22 1207.32,1049.22 v1(1229.53,1027.01)
  Bottom Layer w5.98: U11.5@788,2171 833.08,2171 883.62,2120.46 979.37,2120.46 1260.54,1839.3 1260.54,1167.79 ; v1(1229.53,1027.01) 1229.53,1023.71 1249.2,1043.37 1249.2,1156.45 1260.24,1167.49
PE9: CN7.28 U11.6 U16.34 | length 3098.7
  Top Layer w5.98: CN7.28@0,600 209,600 258,649 337.91,649 351,662.09 351,1029 v1(340,1040) ; v1(1268.89,1031.84) U16.34@1268.89,1077.76 U16.34@1269.11,1077.97
  POWER w5.98: v1(340,1040) 340.99,1039.01 538.65,1039.01 563.85,1064.21 616,1064.21 1236.52,1064.21 v1(1268.89,1031.84)
  Bottom Layer w5.98: U11.6@888,2171 925.55,2133.45 989.98,2133.45 1275.53,1847.9 1275.53,1161.58 ; v1(1268.89,1031.84) 1268.9,1151.12 1275.5,1157.71 1275.5,1161.55
PF0: R54.2 SB19.1 U16.7 | length 280.7
  Top Layer w5.51: R54.2@782,1422.28 793.12,1411.16 v1(874.12,1411.16) ; v1@874.37,1411.41 U16.7@935.23,1411.41
  Top Layer w5.98: v1(874.12,1411.16) v1@874.37,1411.41
  Bottom Layer w5.51: SB19.1@756.4,1423.29 765.24,1423.29 777.37,1411.16 v1(874.12,1411.16)
PF1: R55.2 SB20.1 U16.8 | length 226.5
  Top Layer w5.51: R55.2@783.57,1369.43 805.62,1391.47 v1(811.13,1391.47) 935.12,1391.47 U16.8@935.23,1391.36
  Top Layer w7.87: U16.8@935.23,1391.36 U16.8@935.23,1391.73
  Bottom Layer w5.51: SB20.1@756.8,1365 761.98,1365 788.45,1391.47 v1(811.13,1391.47)
PF3-BOOT0: CN7.9 R50.1 SW1.4 U16.78 | length 2890.4
  Top Layer w5.98: CN7.9@-100,1500 -50.16,1549.84 307.67,1549.84 473.85,1716.03 473.85,1807.85 528,1862 846.05,1862 971.05,1987 v1(971,1987) ; U16.78@1052.36,1608.26 1052.36,1641.91 1052.3,1641.97 1052.3,1732.87 1075.28,1755.86 R50.1@1075.28,1808 1075.28,1976.72 v1(1065,1987) ; v1(1552,1987) 1642,2077 2028.89,2077 2058,2047.89 SW1.4@2058,2013
  POWER w5.98: v1(971,1987) v1(1065,1987) v1(1552,1987)
STLK_LED: R6.1 R7.2 U2.30 | length 951.1
  Top Layer w5.98: v1(1039.08,3226.81) 1050.43,3238.16 U2.30@1096.32,3238.16
  Top Layer w10: v1(1304.73,3558.01) 1382.98,3558.01 1449.78,3491.21 R6.1@1494.19,3491.21 R7.2@1554.19,3491.21
  POWER w10: v1(1039.08,3226.81) 1057.5,3208.39 1286.12,3208.39 v1(1304.73,3227.01)
  Bottom Layer w10: v1(1304.73,3227.01) 1304.73,3227.1 v1(1304.73,3558.01)
STLK_NRST: C17.2 JP4.1 U2.7 | length 1144.2
  Top Layer w5.98: v1(557.88,2986) 528.97,2986 489.28,3025.69 489.28,3107.63 521.55,3139.9 C17.2@571.17,3139.9 661.11,3139.9 724,3202.79 724,3229.81 732.35,3238.16 U2.7@761.68,3238.16
  Bottom Layer w5.98: JP4.1@0,2800 59,2800 151.6,2892.6 464.49,2892.6 v1(557.88,2986)
STLK_OSC_IN: C7.2 U2.5 X1.2 | length 259.8
  Top Layer w5.98: C7.2@518.41,3317.56 598.93,3317.56 610.93,3305.55 665.66,3305.55 693.68,3277.53 U2.5@761.68,3277.53
STLK_OSC_OUT: C8.1 U2.6 X1.1 | length 262.4
  Top Layer w5.98: C8.1@517.82,3213.03 587.41,3213.03 X1.1@605.13,3230.75 664.08,3230.75 691.18,3257.84 U2.6@761.68,3257.84
STLK_SWCLK: CN3.2 U2.37 | length 519.2
  Top Layer w5.98: CN3.2@974.96,3708.25 974.96,3644.87 996.07,3623.76 1132.09,3623.76 1154.34,3601.51 1154.34,3509.68 1108.77,3464.11 1068.12,3464.11 1037.27,3433.26 U2.37@1037.27,3415.32
STLK_SWDIO: CN3.4 U2.34 | length 478.7
  Top Layer w5.98: U2.34@1096.32,3316.9 1062.38,3316.9 1054.17,3325.1 1054.17,3386.59 1174.96,3507.37 CN3.4@1174.96,3708.25
STLK_USB_N: CN1.A7 CN1.B7 U2.32 U3.3 U3.4 | length 1123.4
  Top Layer w10.63: U2.32@1096.32,3277.53 1327.79,3277.53 1383.77,3333.5 1611.62,3333.5 1639.77,3305.35 U3.3@1656.45,3305.35 U3.4@1747,3305.35 1764.28,3305.35 1816.94,3358.01 v1(1893.02,3358.01) ; 1892.98,3415.55 v1(1892.98,3477.36) ; v1(1893.02,3404.96) 1893.02,3415.52 ; v1@1895.43,3477.4 CN1.A7@1895.43,3505.75 ; CN1.B7@1924.96,3572.68 1924.96,3553.14 1935,3543.1 v1(1937.17,3543.1)
  GND w10.63: v1@1935.29,3543.1 v1(1937.17,3543.1)
  Bottom Layer w10.63: v1(1892.98,3477.36) 1893.72,3477.36 1893.72,3499.65 v1(1937.17,3543.1) ; v1(1893.02,3358.01) v1(1893.02,3404.96)
STLK_USB_P: CN1.A6 CN1.B6 R8.1 U2.33 U3.1 U3.6 | length 1220.9
  Top Layer w10.63: U2.33@1096.32,3297.21 1321.31,3297.21 1376.1,3352.01 1471.96,3352.01 ; R8.1@1393.72,3500 1471.96,3421.76 1471.96,3352.01 ; CN1.B6@1905.27,3572.68 1905.27,3544.97 1915.12,3535.12 CN1.A6@1915.12,3505.75 1915.12,3399.74 1915.07,3399.69 1915.07,3395.83 1899.4,3380.16 U3.6@1747,3380.16 U3.1@1656.45,3380.16 1639.77,3380.16 1611.62,3352.01 1471.96,3352.01
STLK_VCP_RX: R25.1 U2.13 U21.3 | length 838.1
  Top Layer w5.98: R25.1@296.94,3097.58 393.61,3097.58 v1(393.9,3097.28) 393.9,3035.1 522.44,2906.56 798.06,2906.56 820.73,2929.23 U2.13@820.73,3080.68
  Bottom Layer w5.98: U21.3@356,3097.29 v1(393.9,3097.28)
STLK_VCP_TX: R33.1 U2.12 | length 225.4
  Top Layer w5.98: R33.1@646.72,3009 686.53,3009 698.92,3021.4 698.92,3117.46 721.2,3139.73 U2.12@761.68,3139.73
T_PWR_EN: R21.1 U2.28 U7.4 | length 1179.4
  Top Layer w5.98: U2.28@1096.32,3198.79 1154.51,3198.79 1198.24,3155.06 v1(1395.18,3155.06) ; R21.1@2074.55,3174.94 R21.1@2074.55,3177.1 v1(2113.82,3216.37) U7.4@2174.56,3216.37
  POWER w5.98: v1(1395.18,3155.06) 2052.51,3155.06 v1(2113.82,3216.37)
T_PWR_EXT: R3.1 R4.1 U2.39 | length 142.3
  Top Layer w5.98: R3.1@954,3514.28 R4.1@997,3514.28 997.9,3513.39 U2.39@997.9,3415.32
T_SWCLK: R34.1 U2.15 U2.22 U2.26 | length 475.3
  Top Layer w5.98: U2.15@860.1,3080.68 860.1,3133.36 886.52,3159.78 1095.96,3159.78 U2.26@1096.32,3159.42 ; R34.1@983.77,2990 983.77,3027.79 997.9,3041.92 U2.22@997.9,3080.68 997.9,3159.43
T_SWDIO_IN: U2.25 U20.2 | length 1196.1
  Top Layer w5.98: v1(416.84,3341.77) 443.9,3314.7 443.9,3048.33 525.46,2966.77 694.99,2966.77 726.88,2998.66 v1(726.88,3103.09) ; v1(1077.96,3102.6) 1096.32,3120.96 U2.25@1096.32,3139.73
  POWER w5.98: v1@727.37,3102.6 v1(1077.96,3102.6)
  Bottom Layer w5.98: U20.2@356,3341.84 356,3341.94 416.67,3341.94 v1(416.84,3341.77) ; v1(726.88,3103.09) v1@727.37,3102.6
T_SWDIO_OUT: R35.1 U2.27 | length 457.7
  Top Layer w5.98: R35.1@779.41,2985.4 779.41,3088.75 869.76,3179.1 U2.27@1096.32,3179.1
T_SWO: R18.1 U2.16 U2.31 U20.3 | length 1531.3
  Top Layer w5.98: R18.1@296.94,3321.34 390.12,3321.34 429.63,3281.83 429.63,3043.37 524.44,2948.56 703.45,2948.56 750.11,2995.21 v1@750.11,3021.3 ; v1(750.3,3021.49) v1@750.11,3021.3 ; U2.16@879.79,3080.68 879.79,3021.24 v1(879.93,3021.1) ; U2.31@1096.32,3257.84 927.3,3257.84 750.11,3080.65 v1@750.11,3021.3
  POWER w5.98: v1@750.7,3021.1 v1(879.93,3021.1)
  Bottom Layer w5.98: U20.3@356,3322.16 389.31,3322.16 v1(415.26,3296.2) ; v1(750.3,3021.49) v1@750.7,3021.1
T_VCC: R28.1 R29.2 | length 38.2
  Top Layer w10: R28.1@572.72,3057 R29.2@610.93,3057
T_VCC_AIN: R24.1 R29.1 U2.10 | length 193.6
  Top Layer w10: R29.1@646.72,3056.65 R24.1@646.72,3104.3 721.52,3179.1 U2.10@761.68,3179.1
TS_PAD: R56.2 TS1.TKEY | length 847.5
  Top Layer w4.72: TS1.TKEY@1650,535.43 1650,672.03 1811,833.03 1811,1190 1796.04,1204.96 R56.2@1690.95,1204.96
TS_SHIELD: R60.2 TS1.SHIELD | length 1812
  Top Layer w3.94: R60.2@1368,859.57 1368,768 1453.1,682.9 1627.83,682.9 ; TS1.SHIELD@1639.76,535.43 1639.76,544.43 1627.83,556.36 1627.83,682.9 ; TS1.SHIELD@1660.24,535.43 1660.24,544.43 1672.17,556.36 1672.17,661.17 1833,822 1833,828 ; v1@1789,1179 1789,844.07 1627.83,682.9 ; 1833.17,828 v1(1833.17,1174)
  other v1: 1900,-16.13 1384.74,-14.85 1616.04,509.17 1385.04,513.4 1890.06,515.37 1789,1174
USB_RENUMn: R1.2 U2.38 | length 112
  Top Layer w5.98: U2.38@1017.58,3415.32 1017.58,3485.83 R1.2@1046.9,3515.14
VBAT: C28.1 C34.2 CN7.35 CN11.1 SB6.2 U16.3 | length 3798
  Top Layer w10: U16.3@935.23,1489.96 U16.3@935.23,1490.15
  Top Layer w15.75: v2(-159.54,2054.54) -159.54,2187.31 C28.1@-96.85,2250 -96.85,2453.15 0,2550 CN11.1@0,2600 ; v2(317,1407.48) 338.29,1407.48 607.81,1677 v2(614.57,1677) 629.57,1692 SB6.2@650.69,1692 650.76,1692 694.72,1648.04 C34.2@694.72,1641 ; C34.2@702.96,1640.98 723.83,1640.98 745.29,1619.53 782.41,1619.53 861.9,1540.03 861.9,1511.15 880.81,1492.25
  POWER w15.75: v2(-140,1450) 274.48,1450 v2(317,1407.48)
  Bottom Layer w15.75: v2(-159.54,2054.54) -159.54,1469.54 ; CN7.35@-100,200 -159.54,259.54 -159.54,1430.46 ; -159.54,1430.46 -159.54,1469.54 ; -159.54,1430.46 v2(-140,1450) -159.54,1469.54
VBUS: C3.1 C5.1 CN1.A4 CN1.A9 CN1.B4 CN1.B9 R13.2 U4.1 U5.B3 U5.C2 U5.C3 | length 729.6
  Top Layer w8.66: U5.B3@2179.3,3359.51 U5.C3@2179.3,3375.25 U5.C2@2195.04,3375.25
  Top Layer w11.81: CN1.A4@1954.49,3505.75 1954.49,3424.29 C5.1@2002.81,3375.97 ; C5.1@2007.1,3373 2050.95,3373 2055.77,3377.83 U4.1@2055.77,3380.09 ; C3.1@2189.83,3417.29 R13.2@2232.74,3417.29
  Top Layer w12.6: CN1.A9@1856.06,3505.75 v1(1856.06,3536.05) 1865.9,3545.89 CN1.B4@1865.9,3572.68 ; CN1.A4@1954.49,3505.75 1954.49,3527.85 v1(1964.33,3537.69) CN1.B9@1964.33,3572.68
  Top Layer w23.62: U4.1@2050.96,3381.25 2050.96,3401.06 2067.88,3417.98 C3.1@2179.5,3417.98
  POWER w12.6: v1(1856.06,3536.05) 1856.06,3548.81 1879.93,3572.68 1945.97,3572.68 1964.33,3554.32 v1(1964.33,3537.69)
VBUS2: C52.1 C53.1 CN14.A4 CN14.A9 CN14.B4 CN14.B9 R62.2 U17.B3 U17.C2 U17.C3 U19.1 | length 703.8
  Top Layer w8.66: 913.88,388 931.59,405.71 931.59,417.81 U17.C2@931.77,418 U17.C3@947.52,418 U17.B3@947.52,433.75
  Top Layer w12.6: CN14.B9@690.94,134.06 v1(690.94,161.94) 700.79,171.79 CN14.A4@700.79,200.98 ; CN14.B4@789.37,134.06 789.37,154.03 799.21,163.88 CN14.A9@799.21,200.98 799.21,219.79 813.42,234 876.9,234 U19.1@912.9,270 912.9,361.52 C52.1@913.88,362.5 913.88,388 ; 800.21,170 v3(817,170) ; R62.2@867.78,351 C52.1@902.38,351
  Bottom Layer w12.6: v1(690.94,161.94) 690.94,148.06 704,135 798.92,135 817,153.08 v3(817,170)
VBUS_STLK: C4.2 C14.2 D1.1 JP3.9 R12.2 R20.2 R21.2 R22.2 U5.A2 U5.A3 U5.B2 U7.5 | length 1873.1
  Top Layer w8.66: U5.A3@2179.3,3343.76 U5.A2@2195.04,3343.76 U5.B2@2195.04,3359.51
  Top Layer w11.81: R12.2@1393.72,3425 v1@1419.85,3425 ; 2110.81,3290.17 2398.95,3290.17 2464.51,3224.61 R20.2@2464.51,3189.49 R22.2@2464.51,3146.49
  Top Layer w19.68: D1.1@1948.59,3208.73 2027.77,3208.73 ; JP3.9@2031,3000 2031,3210.36 2110.81,3290.17 C4.2@2110.81,3325.69 ; 2031.73,3141.57 U7.5@2174.56,3141.57
  POWER w11.81: v1(1420.77,3209.68) 1420.87,3209.58 v1(1980.26,3209.58)
  Bottom Layer w11.81: v1(1420.77,3209.68) v1(1420.77,3425.92)
VDD: C26.2 C55.1 C57.1 CN2.1 CN4.3 CN6.2 CN6.4 CN7.18 JP6.1 JP7.2 L1.2 R28.2 R45.1 R58.1 SW1.5 U9.4 U12.8 U20.8 U21.8 | length 7868
  Top Layer w5.98: U12.8@2068.58,2600.25 2099.5,2600.25 2106,2593.75
  Top Layer w10: v1(493,1158) 515.55,1158 R58.1@515.76,1158.21 ; v1(519,3035.27) 537.28,3053.55 R28.2@537.28,3057
  Top Layer w11.81: v2(1878.94,2459.78) 1862.26,2443.1 1862.26,2294.47 1903.04,2253.7 2034.46,2253.7 2058,2277.24 SW1.5@2058,2313
  Top Layer w15.75: CN4.3@-53,3264 -118.09,3264 -134.44,3280.35 -134.44,3366.47 -67.61,3433.31 v2@168.51,3433.31 ; CN2.1@168.51,3617.51 CN2.1@174,3623 176.88,3620.12 172.87,3616.11 172.96,3616.02 v2(172.96,3433.25) ; v1(329.43,2937.44) 329.42,2955.26 U9.4@329.42,2955.66 ; v2(329.83,2461.36) U9.4@329.83,2955.26
  Top Layer w19.68: CN7.18@0,1100 CN6.4@200,1100 ; JP6.1@450,1982 497.32,1934.68 819.68,1934.68 JP7.2@875,1990 ; v2(1878.94,2459.78) C26.2@1878.94,2538.62 ; C26.2@1879.04,2538.72 L1.2@1879.04,2614.7 ; R45.1@2084,2547.72 2105,2568.72 v2(2105,2572)
  POWER w10: CN6.4@200,1100 435,1100 v1(493,1158)
  POWER w15.75: v2(110.74,1878.09) 113.6,1880.95 348.95,1880.95 JP6.1@450,1982
  POWER w19.68: v2(329.83,2461.36) 940,2461.36 ; JP7.2@875,1982 940,2047 940,2461.36 ; v2@1878.94,2461.36 940,2461.36 ; v2@1883.67,2459.78 2001.39,2459.78 2105,2563.4 v2(2105,2572)
  Bottom Layer w10: 174.96,3178.25 176.18,3179.47 ; v1(329.43,2937.44) 421.17,2937.44 v1(519,3035.27)
  Bottom Layer w15.75: CN7.18@0,1100 52.44,1100 75.99,1123.55 75.99,1843.34 v2(110.74,1878.09) ; 178.23,3181.52 C57.1@233.95,3181.52 ; CN6.4@200,1100 253,1100 274,1121 274,1277.23 251.23,1300 CN6.2@200,1300 ; U20.8@233.57,3364.11 233.57,3407.52 ; C55.1@233.57,3419.35 219.66,3433.25 v2(172.96,3433.25) 172.96,2986.53 172.87,2986.43 221.86,2937.44 v1(329.43,2937.44) ; U21.8@233.95,3140.69 C57.1@233.95,3181.52 ; C57.1@234.24,3187.34 234.24,3181.52 C57.1@233.95,3181.52
VDD_LP: C29.2 CN13.7 JP6.2 R46.2 R48.2 R49.2 U15.3 | length 3585.9
  Top Layer w5.98: R46.2@1717.72,1942.31 R46.2@1717.72,1943 ; U15.3@1765.12,1897.28 1789.28,1897.28 1816.3,1924.3 1843.4,1924.3 1867,1900.7 1867,1827 1844.37,1804.37 R48.2@1819,1804.37
  Top Layer w7.87: R49.2@1650,1828.72 1624.22,1828.72 1615,1837.94 1615,1918 1664.71,1967.72 1698.88,1967.72 1717.72,1948.88 R46.2@1717.72,1943
  Top Layer w15.75: R46.2@1717.72,1943 v2(1739,1943) 1757.28,1943 C29.2@1759.28,1945 ; U15.3@1761,1900 1761,1933.28
  POWER w15.75: JP6.2@550,1982 601.76,1930.24 1724.74,1930.24 v2@1737.5,1943
  Bottom Layer w15.75: CN13.7@1200,600 1234,634 1592,634 1750.5,792.5 1750.5,1931.5 v2(1739,1943)
VDD_MCU: C31.2 C33.2 C48.2 C49.2 CN7.14 JP6.3 JP7.1 R59.1 SB6.1 SB15.1 U16.2 U16.22 U16.38 | length 4254.1
  Top Layer w11.81: U16.2@935.23,1509.84 935.4,1510 v2(994,1510) ; C48.2@1028.35,992.66 1032.67,996.98 U16.22@1032.67,1077.76 ; 1347.63,1016.94 U16.38@1347.63,1077.76
  Top Layer w15.75: v2(308,1350) 327,1350 v2(488,1511) ; v2(583,973) 607.41,973 R59.1@624.37,989.97 ; SB6.1@694,1692 736.19,1692 v2(737.11,1691.08) 767.52,1691.08 C31.2@770.44,1694 770.44,1664.56 781,1654 C33.2@789.28,1654 789.28,1647.34 884.65,1551.97 884.65,1520.58 893.51,1511.72
  Top Layer w19.68: v2(1004,992.6) 1028.3,992.6 C48.2@1028.35,992.66 ; v2(1224,940) 1243.68,959.68 C49.2@1280,959.72
  POWER w15.75: CN7.14@0,1300 78,1300 128,1350 v2(308,1350) ; v2(583,973) 588,973 607.66,992.66 v2@1002.66,992.66 ; 882.01,992.57 1002.58,992.57 v2@1002.66,992.66 ; v2(994,1510) 1052.7,1510 1125.7,1583 v2(1656,1583) ; v2(1224,940) 1230.58,940 1230.79,939.79 1080.21,939.79 1027.34,992.66 1027.29,992.6 v2(1004,992.6) v2@1002.72,992.6 ; v2@1002.66,992.66 v2@1002.72,992.6 ; v2@1002.66,992.66 v2@1002.72,992.6
  Bottom Layer w15.75: 650,1736 694.92,1691.08 v2(737.11,1691.08) ; JP6.3@650,1982 JP7.1@775,1982 ; SB15.1@1609.68,1596 1622.68,1583 v2(1656,1583)
  Bottom Layer w19.68: v2(583,973) 578.88,977.12 516.88,977.12 467.3,1026.7 467.3,1251.3 488,1272 v2(488,1511) 488,1693.44 530.56,1736 650,1736 JP6.3@650,1982
VDDUSB: C35.2 CN7.7 SB14.2 SB15.2 U16.60 | length 2460.9
  Top Layer w11.81: U16.60@1464.76,1529.52 1509.81,1529.52 1571.27,1590.98
  Top Layer w15.75: CN7.7@-100,1600 -50,1650 33.31,1650 100.31,1583 297.2,1583 443,1728.8 443,1835.5 508.5,1901 v2(821,1901) ; v2(1567,1635) 1567,1638 1606.21,1677.21 v2(1606.21,1789.51)
  Top Layer w17.72: v2(1567,1635) 1567,1621.69 1577.28,1611.4 C35.2@1577.28,1604
  POWER w15.75: v2(821,1901) v2(1590,1901)
  Bottom Layer w15.75: 1566.38,1602 SB14.2@1566.38,1674 ; v2(1590,1901) 1606.21,1884.79 v2(1606.21,1789.51)
VIN: C30.2 CN6.8 U14.3 | length 1447.7
  Top Layer w15.75: v2(294.79,1784.78) 397.45,1784.78 C30.2@398.83,1783.4 398.83,1749.81 365.19,1716.18 U14.3@317.63,1716.18
  Bottom Layer w15.75: CN6.8@200,700 143.22,756.78 143.22,1707.12 220.87,1784.78 v2(294.79,1784.78)
VREF: C44.2 C45.1 C58.2 CN10.10 R57.1 SB12.1 SB17.2 U16.15 | length 2539.6
  Top Layer w5.98: 874.67,1253.93 U16.15@935.23,1253.93
  Top Layer w11.81: v1(495,1203) 515.94,1203 R57.1@516.15,1202.79
  Top Layer w15.75: 526.32,1027 514,1027 514,1053 v1(518.86,1057.86) 523.72,1062.72 554.21,1062.72 571.26,1079.77 C45.1@571.26,1095.12 ; C45.1@574.22,1086.26 C44.2@605.72,1086.26 706.77,1086.26 740.73,1120.21 740.73,1137.64 v2(824.09,1221) 855.06,1251.97
  POWER w15.75: v2(824.09,1221) 905.59,1302.5 1022.6,1302.5 1167.09,1446.99 1624.8,1446.99 1625.77,1446.03 1826.03,1446.03 v2(1890,1510) 2175.23,1510 2215.23,1550 2350,1550 CN10.10@2400,1500
  Bottom Layer w11.81: v1(495,1203) 498,1203 514.76,1186.24 514.76,1148.99 514.17,1148.39 514.17,1062.55 v1(518.86,1057.86)
  Bottom Layer w15.75: v2(1890,1510) 1913.28,1510 C58.2@1915.28,1508 1915.28,1536.72 1898.24,1553.76 SB17.2@1898.24,1560
pads on no net: B2.NPTH1 B2.NPTH2 CN1.0 CN1.A2 CN1.A3 CN1.A8 CN1.A10 CN1.A11 CN1.B2 CN1.B3 CN1.B8 CN1.B10 CN1.B11 CN2.7 CN2.8 CN2.9 CN2.11 CN2.12 CN2.13 CN4.0 CN4.1 CN4.2 CN4.10 CN14.0 CN14.A2 CN14.A3 CN14.A8 CN14.A10 CN14.A11 CN14.B2 CN14.B3 CN14.B8 CN14.B10 CN14.B11 Designator1.1 Designator2.1 Designator3.1 U2.4 U2.11 U2.14 U2.17 U2.19 U2.21 U2.40 U2.41 U2.42 U2.43 U2.45 U2.46 U3.5 U15.7 U16.0 U18.5 U21.2 X3.2 X3.4

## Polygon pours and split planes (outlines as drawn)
GND on Top Layer "GND" (solid, remove dead copper, pour order 10): -227.95,-41.01 ccw(c-149.21,-41.01) -149.21,-119.75 1681.5,-119.75 2449.22,-119.75 ccw(c2449.22,-41.01) 2527.96,-41.01 2527.96,3738.52 ccw(c2449.22,3738.52) 2449.22,3817.26 -149.21,3817.26 ccw(c-149.21,3738.52) -227.95,3738.52 -227.95,2084.98 -227.95,2084
TS_SHIELD on Top Layer "TS_SHIELD_1" (hatched 45Degree grid 40 track 6, remove dead copper, pour order 0): 1374.41,-25.59 1374.41,525.59 1641.73,525.59 1641.73,452.59 ccw(c1650,250) 1658.27,452.59 1658.27,525.59 1925.59,525.59 1925.59,-25.59
GND on GND "GND" (solid, remove dead copper, pour order 8): -227.95,-41.01 ccw(c-149.21,-41.01) -149.21,-119.75 1681.5,-119.75 2449.22,-119.75 ccw(c2449.22,-41.01) 2527.96,-41.01 2527.96,3738.52 ccw(c2449.22,3738.52) 2449.22,3817.26 -149.21,3817.26 ccw(c-149.21,3738.52) -227.95,3738.52 -227.95,2084.98 -227.95,2084
TS_SHIELD on GND "TS_SHIELD_1" (hatched 45Degree grid 41.73 track 5.98, remove dead copper, pour order 4): 1428.59,1262.31 1435.29,1269 1781.5,1269 1842,1208.5 1842,823.58 1675.15,656.72 1675.15,512 1619.97,512 1611,520.97 1611,641.29 1591.29,661 1442.19,661 1341,761.84 1341,1046.36 1348.39,1053.75 1388.24,1053.76 1397,1045 1397,790.14 1482.14,705 1644,705 1781,842 1781,1172 1765,1188 1644,1188 1626,1206 1626,1219 1618,1227 1434,1227 1428.59,1232.41
TS_SHIELD on GND "TS_SHIELD_3" (hatched 45Degree grid 41.73 track 5.98, remove dead copper, pour order 2): 1374.41,525.59 1374.41,-25.59 1925.59,-25.59 1925.59,525.59
GND on POWER "GND" (solid, remove dead copper, pour order 6): -227.95,-41.01 ccw(c-149.21,-41.01) -149.21,-119.75 1681.5,-119.75 2449.22,-119.75 ccw(c2449.22,-41.01) 2527.96,-41.01 2527.96,3738.52 ccw(c2449.22,3738.52) 2449.22,3817.26 -149.21,3817.26 ccw(c-149.21,3738.52) -227.95,3738.52 -227.95,2084.98 -227.95,2084
GND on Bottom Layer "GND" (solid, remove dead copper, pour order 12): -227.95,-41.01 ccw(c-149.21,-41.01) -149.21,-119.75 1681.5,-119.75 2449.22,-119.75 ccw(c2449.22,-41.01) 2527.96,-41.01 2527.96,3738.52 ccw(c2449.22,3738.52) 2449.22,3817.26 -149.21,3817.26 ccw(c-149.21,3738.52) -227.95,3738.52 -227.95,2084.98 -227.95,2084

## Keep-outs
Keep-Out Layer:
  lines w5: -227.95,2084 -227.95,-41.01 ccw(c-149.21,-41.01) -149.21,-119.75 219.69,-119.75 224.81,-119.75 1681.5,-119.75 ; -227.95,2084.98 -227.95,2970.8 -227.95,3738.21 ; -227.95,3738.52 cw(c-149.21,3738.52) -149.21,3817.26 2449.22,3817.26 cw(c2449.22,3738.52) 2527.96,3738.52 ; 2527.96,3738.21 2527.96,2970.81 2527.96,2045.61 2527.96,-41.01 cw(c2449.22,-41.01) 2449.22,-119.75 1681.5,-119.75 ; 1681.5,-119.75 1681.5,-119.75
